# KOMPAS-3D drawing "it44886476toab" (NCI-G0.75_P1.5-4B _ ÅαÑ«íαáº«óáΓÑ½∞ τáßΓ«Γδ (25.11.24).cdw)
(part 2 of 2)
  Кривая без истории:10762
  Кривая без истории:10763
  Кривая без истории:10764
  Кривая без истории:10765
  Кривая без истории:10766
  Кривая без истории:10767
  Кривая без истории:10768
  Кривая без истории:10769
  Кривая без истории:10770
  Кривая без истории:10771
  Кривая без истории:10772
  Кривая без истории:10773
  Кривая без истории:10774
  Кривая без истории:10775
  Кривая без истории:10776
  Кривая без истории:10777
  Кривая без истории:10778
  Кривая без истории:10779
  Кривая без истории:10780
  Кривая без истории:10781
  Кривая без истории:10782
  Кривая без истории:10783
  Кривая без истории:10784
  Кривая без истории:10785
  Кривая без истории:10786
  Кривая без истории:10787
  Кривая без истории:10788
  Кривая без истории:10789
  Кривая без истории:10790
  Кривая без истории:10791
  Кривая без истории:10792
  Кривая без истории:10793
  Кривая без истории:10794
  Кривая без истории:10795
  Кривая без истории:10796
  Кривая без истории:10797
  Кривая без истории:10798
  Кривая без истории:10799
  Кривая без истории:10800
  Кривая без истории:10801
  Кривая без истории:10802
  Кривая без истории:10803
  Кривая без истории:10804
  Кривая без истории:10805
  Кривая без истории:10806
  Кривая без истории:10807
  Кривая без истории:10808
  Кривая без истории:10809
  Кривая без истории:10810
  Кривая без истории:10811
  Кривая без истории:10812
  Кривая без истории:10813
  Кривая без истории:10814
  Кривая без истории:10815
  Кривая без истории:10816
  Кривая без истории:10817
  Кривая без истории:10818
  Кривая без истории:10819
  Кривая без истории:10820
  Кривая без истории:10821
  Кривая без истории:10822
  Кривая без истории:10823
  Кривая без истории:10824
  Кривая без истории:10825
  Кривая без истории:10826
  Кривая без истории:10827
  Кривая без истории:10828
  Кривая без истории:10829
  Кривая без истории:10830
  Кривая без истории:10831
  Кривая без истории:10832
  Кривая без истории:10833
  Кривая без истории:10834
  Кривая без истории:10835
  Кривая без истории:10836
  Кривая без истории:10837
  Кривая без истории:10838
  Кривая без истории:10839
  Кривая без истории:10840
  Кривая без истории:10841
  Кривая без истории:10842
  Кривая без истории:10843
  Кривая без истории:10844
  Кривая без истории:10845
  Кривая без истории:10846
  Кривая без истории:10847
  Кривая без истории:10848
  Кривая без истории:10849
  Кривая без истории:10850
  Кривая без истории:10851
  Кривая без истории:10852
  Кривая без истории:10853
  Кривая без истории:10854
  Кривая без истории:10855
  Кривая без истории:10856
  Кривая без истории:10857
  Кривая без истории:10858
  Кривая без истории:10859
  Кривая без истории:10860
  Кривая без истории:10861
  Кривая без истории:10862
  Кривая без истории:10863
  Кривая без истории:10864
  Кривая без истории:10865
  Кривая без истории:10866
  Кривая без истории:10867
  Кривая без истории:10868
  Кривая без истории:10869
  Кривая без истории:10870
  Кривая без истории:10871
  Кривая без истории:10872
  Кривая без истории:10873
  Кривая без истории:10874
  Кривая без истории:10875
  Кривая без истории:10876
  Кривая без истории:10877
  Кривая без истории:10878
  Кривая без истории:10879
  Кривая без истории:10880
  Кривая без истории:10881
  Кривая без истории:10882
  Кривая без истории:10883
  Кривая без истории:10884
  Кривая без истории:10885
  Кривая без истории:10886
  Кривая без истории:10887
  Кривая без истории:10888
  Кривая без истории:10889
  Кривая без истории:10890
  Кривая без истории:10891
  Кривая без истории:10892
  Кривая без истории:10893
  Кривая без истории:10894
  Кривая без истории:10895
  Кривая без истории:10896
  Кривая без истории:10897
  Кривая без истории:10898
  Кривая без истории:10899
  Кривая без истории:10900
  Кривая без истории:10901
  Кривая без истории:10902
  Кривая без истории:10903
  Кривая без истории:10904
  Кривая без истории:10905
  Кривая без истории:10906
  Кривая без истории:10907
  Кривая без истории:10908
  Кривая без истории:10909
  Кривая без истории:10910
  Кривая без истории:10911
  Кривая без истории:10912
  Кривая без истории:10913
  Кривая без истории:10914
  Кривая без истории:10915
  Кривая без истории:10916
  Кривая без истории:10917
  Кривая без истории:10918
  Кривая без истории:10919
  Кривая без истории:10920
  Кривая без истории:10921
  Кривая без истории:10922
  Кривая без истории:10923
  Кривая без истории:10924
  Кривая без истории:10925
  Кривая без истории:10926
  Кривая без истории:10927
  Кривая без истории:10928
  Кривая без истории:10929
  Кривая без истории:10930
  Кривая без истории:10931
  Кривая без истории:10932
  Кривая без истории:10933
  Кривая без истории:10934
  Кривая без истории:10935
  Кривая без истории:10936
  Кривая без истории:10937
  Кривая без истории:10938
  Кривая без истории:10939
  Кривая без истории:10940
  Кривая без истории:10941
  Кривая без истории:10942
  Кривая без истории:10943
  Кривая без истории:10944
  Кривая без истории:10945
  Кривая без истории:10946
  Кривая без истории:10947
  Кривая без истории:10948
  Кривая без истории:10949
  Кривая без истории:10950
  Кривая без истории:10951
  Кривая без истории:10952
  Кривая без истории:10953
  Кривая без истории:10954
  Кривая без истории:10955
  Кривая без истории:10956
  Кривая без истории:10957
  Кривая без истории:10958
  Кривая без истории:10959
  Кривая без истории:10960
  Кривая без истории:10961
  Кривая без истории:10962
  Кривая без истории:10963
  Кривая без истории:10964
  Кривая без истории:10965
  Кривая без истории:10966
  Кривая без истории:10967
  Кривая без истории:10968
  Кривая без истории:10969
  Кривая без истории:10970
  Кривая без истории:10971
  Кривая без истории:10972
  Кривая без истории:10973
  Кривая без истории:10974
  Кривая без истории:10975
  Кривая без истории:10976
  Кривая без истории:10977
  Кривая без истории:10978
  Кривая без истории:10979
  Кривая без истории:10980
  Кривая без истории:10981
  Кривая без истории:10982
  Кривая без истории:10983
  Кривая без истории:10984
  Кривая без истории:10985
  Кривая без истории:10986
  Кривая без истории:10987
  Кривая без истории:10988
  Кривая без истории:10989
  Кривая без истории:10990
  Кривая без истории:10991
  Кривая без истории:10992
  Кривая без истории:10993
  Кривая без истории:10994
  Кривая без истории:10995
  Кривая без истории:10996
  Кривая без истории:10997
  Кривая без истории:10998
  Кривая без истории:10999
  Кривая без истории:11000
  Кривая без истории:11001
  Кривая без истории:11002
  Кривая без истории:11003
  Кривая без истории:11004
  Кривая без истории:11005
  Кривая без истории:11006
  Кривая без истории:11007
  Кривая без истории:11008
  Кривая без истории:11009
  Кривая без истории:11010
  Кривая без истории:11011
  Кривая без истории:11012
  Кривая без истории:11013
  Кривая без истории:11014
  Кривая без истории:11015
  Кривая без истории:11016
  Кривая без истории:11017
  Кривая без истории:11018
  Кривая без истории:11019
  Кривая без истории:11020
  Кривая без истории:11021
  Кривая без истории:11022
  Кривая без истории:11023
  Кривая без истории:11024
  Кривая без истории:11025
  Кривая без истории:11026
  Кривая без истории:11027
  Кривая без истории:11028
  Кривая без истории:11029
  Кривая без истории:11030
  Кривая без истории:11031
  Кривая без истории:11032
  Кривая без истории:11033
  Кривая без истории:11034
  Кривая без истории:11035
  Кривая без истории:11036
  Кривая без истории:11037
  Кривая без истории:11038
  Кривая без истории:11039
  Кривая без истории:11040
  Кривая без истории:11041
  Кривая без истории:11042
  Кривая без истории:11043
  Кривая без истории:11044
  Кривая без истории:11045
  Кривая без истории:11046
  Кривая без истории:11047
  Кривая без истории:11048
  Кривая без истории:11049
  Кривая без истории:11050
  Кривая без истории:11051
  Кривая без истории:11052
  Кривая без истории:11053
  Кривая без истории:11054
  Кривая без истории:11055
  Кривая без истории:11056
  Кривая без истории:11057
  Кривая без истории:11058
  Кривая без истории:11059
  Кривая без истории:11060
  Кривая без истории:11061
  Кривая без истории:11062
  Кривая без истории:11063
  Кривая без истории:11064
  Кривая без истории:11065
  Кривая без истории:11066
  Кривая без истории:11067
  Кривая без истории:11068
  Кривая без истории:11069
  Кривая без истории:11070
  Кривая без истории:11071
  Кривая без истории:11072
  Кривая без истории:11073
  Кривая без истории:11074
  Кривая без истории:11075
  Кривая без истории:11076
  Кривая без истории:11077
  Кривая без истории:11078
  Кривая без истории:11079
  Кривая без истории:11080
  Кривая без истории:11081
  Кривая без истории:11082
  Кривая без истории:11083
  Кривая без истории:11084
  Кривая без истории:11085
  Кривая без истории:11086
  Кривая без истории:11087
  Кривая без истории:11088
  Кривая без истории:11089
  Кривая без истории:11090
  Кривая без истории:11091
  Кривая без истории:11092
  Кривая без истории:11093
  Кривая без истории:11094
  Кривая без истории:11095
  Кривая без истории:11096
  Кривая без истории:11097
  Кривая без истории:11098
  Кривая без истории:11099
  Кривая без истории:11100
  Кривая без истории:11101
  Кривая без истории:11102
  Кривая без истории:11103
  Кривая без истории:11104
  Кривая без истории:11105
  Кривая без истории:11106
  Кривая без истории:11107
  Кривая без истории:11108
  Кривая без истории:11109
  Кривая без истории:11110
  Кривая без истории:11111
  Кривая без истории:11112
  Кривая без истории:11113
  Кривая без истории:11114
  Кривая без истории:11115
  Кривая без истории:11116
  Кривая без истории:11117
  Кривая без истории:11118
  Кривая без истории:11119
  Кривая без истории:11120
  Кривая без истории:11121
  Кривая без истории:11122
  Кривая без истории:11123
  Кривая без истории:11124
  Кривая без истории:11125
  Кривая без истории:11126
  Кривая без истории:11127
  Кривая без истории:11128
  Кривая без истории:11129
  Кривая без истории:11130
  Кривая без истории:11131
  Кривая без истории:11132
  Кривая без истории:11133
  Кривая без истории:11134
  Кривая без истории:11135
  Кривая без истории:11136
  Кривая без истории:11137
  Кривая без истории:11138
  Кривая без истории:11139
  Кривая без истории:11140
  Кривая без истории:11141
  Кривая без истории:11142
  Кривая без истории:11143
  Кривая без истории:11144
  Кривая без истории:11145
  Кривая без истории:11146
  Кривая без истории:11147
  Кривая без истории:11148
  Кривая без истории:11149
  Кривая без истории:11150
  Кривая без истории:11151
  Кривая без истории:11152
  Кривая без истории:11153
  Кривая без истории:11154
  Кривая без истории:11155
  Кривая без истории:11156
  Кривая без истории:11157
  Кривая без истории:11158
  Кривая без истории:11159
  Кривая без истории:11160
  Кривая без истории:11161
  Кривая без истории:11162
  Кривая без истории:11163
  Кривая без истории:11164
  Кривая без истории:11165
  Кривая без истории:11166
  Кривая без истории:11167
  Кривая без истории:11168
  Кривая без истории:11169
  Кривая без истории:11170
  Кривая без истории:11171
  Кривая без истории:11172
  Кривая без истории:11173
  Кривая без истории:11174
  Кривая без истории:11175
  Кривая без истории:11176
  Кривая без истории:11177
  Кривая без истории:11178
  Кривая без истории:11179
  Кривая без истории:11180
  Кривая без истории:11181
  Кривая без истории:11182
  Кривая без истории:11183
  Кривая без истории:11184
  Кривая без истории:11185
  Кривая без истории:11186
  Кривая без истории:11187
  Кривая без истории:11188
  Кривая без истории:11189
  Кривая без истории:11190
  Кривая без истории:11191
  Кривая без истории:11192
  Кривая без истории:11193
  Кривая без истории:11194
  Кривая без истории:11195
  Кривая без истории:11196
  Кривая без истории:11197
  Кривая без истории:11198
  Кривая без истории:11199
  Кривая без истории:11200
  Кривая без истории:11201
  Кривая без истории:11202
  Кривая без истории:11203
  Кривая без истории:11204
  Кривая без истории:11205
  Кривая без истории:11206
  Кривая без истории:11207
  Кривая без истории:11208
  Кривая без истории:11209
  Кривая без истории:11210
  Кривая без истории:11211
  Кривая без истории:11212
  Кривая без истории:11213
  Кривая без истории:11214
  Кривая без истории:11215
  Кривая без истории:11216
  Кривая без истории:11217
  Кривая без истории:11218
  Кривая без истории:11219
  Кривая без истории:11220
  Кривая без истории:11221
  Кривая без истории:11222
  Кривая без истории:11223
  Кривая без истории:11224
  Кривая без истории:11225
  Кривая без истории:11226
  Кривая без истории:11227
  Кривая без истории:11228
  Кривая без истории:11229
  Кривая без истории:11230
  Кривая без истории:11231
  Кривая без истории:11232
  Кривая без истории:11233
  Кривая без истории:11234
  Кривая без истории:11235
  Кривая без истории:11236
  Кривая без истории:11237
  Кривая без истории:11238
  Кривая без истории:11239
  Кривая без истории:11240
  Кривая без истории:11241
  Кривая без истории:11242
  Кривая без истории:11243
  Кривая без истории:11244
  Кривая без истории:11245
  Кривая без истории:11246
  Кривая без истории:11247
  Кривая без истории:11248
  Кривая без истории:11249
  Кривая без истории:11250
  Кривая без истории:11251
  Кривая без истории:11252
  Кривая без истории:11253
  Кривая без истории:11254
  Кривая без истории:11255
  Кривая без истории:11256
  Кривая без истории:11257
  Кривая без истории:11258
  Кривая без истории:11259
  Кривая без истории:11260
  Кривая без истории:11261
  Кривая без истории:11262
  Кривая без истории:11263
  Кривая без истории:11264
  Кривая без истории:11265
  Кривая без истории:11266
  Кривая без истории:11267
  Кривая без истории:11268
  Кривая без истории:11269
  Кривая без истории:11270
  Кривая без истории:11271
  Кривая без истории:11272
  Кривая без истории:11273
  Кривая без истории:11274
  Кривая без истории:11275
  Кривая без истории:11276
  Кривая без истории:11277
  Кривая без истории:11278
  Кривая без истории:11279
  Кривая без истории:11280
  Кривая без истории:11281
  Кривая без истории:11282
  Кривая без истории:11283
  Кривая без истории:11284
  Кривая без истории:11285
  Кривая без истории:11286
  Кривая без истории:11287
  Кривая без истории:11288
  Кривая без истории:11289
  Кривая без истории:11290
  Кривая без истории:11291
  Кривая без истории:11292
  Кривая без истории:11293
  Кривая без истории:11294
  Кривая без истории:11295
  Кривая без истории:11296
  Кривая без истории:11297
  Кривая без истории:11298
  Кривая без истории:11299
  Кривая без истории:11300
  Кривая без истории:11301
  Кривая без истории:11302
  Кривая без истории:11303
  Кривая без истории:11304
  Кривая без истории:11305
  Кривая без истории:11306
  Кривая без истории:11307
  Кривая без истории:11308
  Кривая без истории:11309
  Кривая без истории:11310
  Кривая без истории:11311
  Кривая без истории:11312
  Кривая без истории:11313
  Кривая без истории:11314
  Кривая без истории:11315
  Кривая без истории:11316
  Кривая без истории:11317
  Кривая без истории:11318
  Кривая без истории:11319
  Кривая без истории:11320
  Кривая без истории:11321
  Кривая без истории:11322
  Кривая без истории:11323
  Кривая без истории:11324
  Кривая без истории:11325
  Кривая без истории:11326
  Кривая без истории:11327
  Кривая без истории:11328
  Кривая без истории:11329
  Кривая без истории:11330
  Кривая без истории:11331
  Кривая без истории:11332
  Кривая без истории:11333
  Кривая без истории:11334
  Кривая без истории:11335
  Кривая без истории:11336
  Кривая без истории:11337
  Кривая без истории:11338
  Кривая без истории:11339
  Кривая без истории:11340
  Кривая без истории:11341
  Кривая без истории:11342
  Кривая без истории:11343
  Кривая без истории:11344
  Кривая без истории:11345
  Кривая без истории:11346
  Кривая без истории:11347
  Кривая без истории:11348
  Кривая без истории:11349
  Кривая без истории:11350
  Кривая без истории:11351
  Кривая без истории:11352
  Кривая без истории:11353
  Кривая без истории:11354
  Кривая без истории:11355
  Кривая без истории:11356
  Кривая без истории:11357
  Кривая без истории:11358
  Кривая без истории:11359
  Кривая без истории:11360
  Кривая без истории:11361
  Кривая без истории:11362
  Кривая без истории:11363
  Кривая без истории:11364
  Кривая без истории:11365
  Кривая без истории:11366
  Кривая без истории:11367
  Кривая без истории:11368
  Кривая без истории:11369
  Кривая без истории:11370
  Кривая без истории:11371
  Кривая без истории:11372
  Кривая без истории:11373
  Кривая без истории:11374
  Кривая без истории:11375
  Кривая без истории:11376
  Кривая без истории:11377
  Кривая без истории:11378
  Кривая без истории:11379
  Кривая без истории:11380
  Кривая без истории:11381
  Кривая без истории:11382
  Кривая без истории:11383
  Кривая без истории:11384
  Кривая без истории:11385
  Кривая без истории:11386
  Кривая без истории:11387
  Кривая без истории:11388
  Кривая без истории:11389
  Кривая без истории:11390
  Кривая без истории:11391
  Кривая без истории:11392
  Кривая без истории:11393
  Кривая без истории:11394
  Кривая без истории:11395
  Кривая без истории:11396
  Кривая без истории:11397
  Кривая без истории:11398
  Кривая без истории:11399
  Кривая без истории:11400
  Кривая без истории:11401
  Кривая без истории:11402
  Кривая без истории:11403
  Кривая без истории:11404
  Кривая без истории:11405
  Кривая без истории:11406
  Кривая без истории:11407
  Кривая без истории:11408
  Кривая без истории:11409
  Кривая без истории:11410
  Кривая без истории:11411
  Кривая без истории:11412
  Кривая без истории:11413
  Кривая без истории:11414
  Кривая без истории:11415
  Кривая без истории:11416
  Кривая без истории:11417
  Кривая без истории:11418
  Кривая без истории:11419
  Кривая без истории:11420
  Кривая без истории:11421
  Кривая без истории:11422
  Кривая без истории:11423
  Кривая без истории:11424
  Кривая без истории:11425
  Кривая без истории:11426
  Кривая без истории:11427
  Кривая без истории:11428
  Кривая без истории:11429
  Кривая без истории:11430
  Кривая без истории:11431
  Кривая без истории:11432
  Кривая без истории:11433
  Кривая без истории:11434
  Кривая без истории:11435
  Кривая без истории:11436
  Кривая без истории:11437
  Кривая без истории:11438
  Кривая без истории:11439
  Кривая без истории:11440
  Кривая без истории:11441
  Кривая без истории:11442
  Кривая без истории:11443
  Кривая без истории:11444
  Кривая без истории:11445
  Кривая без истории:11446
  Кривая без истории:11447
  Кривая без истории:11448
  Кривая без истории:11449
  Кривая без истории:11450
  Кривая без истории:11451
  Кривая без истории:11452
  Кривая без истории:11453
  Кривая без истории:11454
  Кривая без истории:11455
  Кривая без истории:11456
  Кривая без истории:11457
  Кривая без истории:11458
  Кривая без истории:11459
  Кривая без истории:11460
  Кривая без истории:11461
  Кривая без истории:11462
  Кривая без истории:11463
  Кривая без истории:11464
  Кривая без истории:11465
  Кривая без истории:11466
  Кривая без истории:11467
  Кривая без истории:11468
  Кривая без истории:11469
  Кривая без истории:11470
  Кривая без истории:11471
  Кривая без истории:11472
  Кривая без истории:11473
  Кривая без истории:11474
  Кривая без истории:11475
  Кривая без истории:11476
  Кривая без истории:11477
  Кривая без истории:11478
  Кривая без истории:11479
  Кривая без истории:11480
  Кривая без истории:11481
  Кривая без истории:11482
  Кривая без истории:11483
  Кривая без истории:11484
  Кривая без истории:11485
  Кривая без истории:11486
  Кривая без истории:11487
  Кривая без истории:11488
  Кривая без истории:11489
  Кривая без истории:11490
  Кривая без истории:11491
  Кривая без истории:11492
  Кривая без истории:11493
  Кривая без истории:11494
  Кривая без истории:11495
  Кривая без истории:11496
  Кривая без истории:11497
  Кривая без истории:11498
  Кривая без истории:11499
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Dimensions and other numbers on the sheet: 1:1; 1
